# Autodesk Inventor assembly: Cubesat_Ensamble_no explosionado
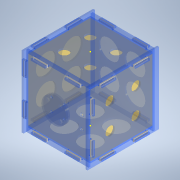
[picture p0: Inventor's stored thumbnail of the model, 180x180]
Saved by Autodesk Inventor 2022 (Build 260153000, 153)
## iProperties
Created: 2022-05
Part Number: Cubesat_Ensamble_no explosionado
Document SubType Name: Assembly
Designer: valen
Author: valen
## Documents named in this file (11)
- C:\Users\valen\Desktop\Estandar CubeSat - Programa AVES-20220531T050024Z-001\Estandar CubeSat - Programa AVES\3D - MODELS\IPT(Autodesk Inventor)\Cubesat_Ensamble_no explosionado.iam
- C:\Users\valen\Desktop\Estandar CubeSat - Programa AVES-20220531T050024Z-001\Estandar CubeSat - Programa AVES\3D - MODELS\IPT(Autodesk Inventor)\Volumen interno .ipt
- C:\Users\valen\Desktop\Estandar CubeSat - Programa AVES-20220531T050024Z-001\Estandar CubeSat - Programa AVES\3D - MODELS\IPT(Autodesk Inventor)\1.Frontal.ipt
- C:\Users\valen\Desktop\Estandar CubeSat - Programa AVES-20220531T050024Z-001\Estandar CubeSat - Programa AVES\3D - MODELS\IPT(Autodesk Inventor)\3.Posterior.ipt
- C:\Users\valen\Desktop\Estandar CubeSat - Programa AVES-20220531T050024Z-001\Estandar CubeSat - Programa AVES\3D - MODELS\IPT(Autodesk Inventor)\2.Lateral derecha .ipt
- C:\Users\valen\Desktop\Estandar CubeSat - Programa AVES-20220531T050024Z-001\Estandar CubeSat - Programa AVES\3D - MODELS\IPT(Autodesk Inventor)\4.Lateral izquierda.ipt
- C:\Users\valen\Desktop\Estandar CubeSat - Programa AVES-20220531T050024Z-001\Estandar CubeSat - Programa AVES\3D - MODELS\IPT(Autodesk Inventor)\6.Inferior.ipt
- C:\Users\valen\Desktop\Estandar CubeSat - Programa AVES-20220531T050024Z-001\Estandar CubeSat - Programa AVES\3D - MODELS\IPT(Autodesk Inventor)\5.Superior.ipt
- C:\Users\valen\Desktop\Estandar CubeSat - Programa AVES-20220531T050024Z-001\Estandar CubeSat - Programa AVES\3D - MODELS\IPT(Autodesk Inventor)\7. Arandela.ipt
- C:\Users\valen\Desktop\Estandar CubeSat - Programa AVES-20220531T050024Z-001\Estandar CubeSat - Programa AVES\3D - MODELS\IPT(Autodesk Inventor)\8. Soporte tuercas.ipt
- C:\Users\valen\Desktop\Estandar CubeSat - Programa AVES-20220531T050024Z-001\Estandar CubeSat - Programa AVES\3D - MODELS\IPT(Autodesk Inventor)\Oring.ipt
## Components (29 placed, 10 different names)
1. Volumen interno :1 — Flush:1, Mate:1, Flush:2, Flush:3, Flush:4, Mate:2, Flush:5, Mate:3, Mate:4, Mate:5, Mate:6, Mate:7, Flush:7, Flush:8, Mate:8, Flush:9
2. 1.Frontal:1 — Flush:1, Mate:1, Flush:3, Flush:10, Mate:16, Mate:18, Mate:20, Mate:22, Mate:24
3. 2.Lateral derecha :1 — Mate:3, Mate:4, Mate:5, Flush:6, Mate:23, Flush:14, Mate:25, Flush:15, Mate:27, Flush:16, Mate:29, Flush:17, Mate:39, Flush:22, Mate:41, Flush:23, Mate:47, Flush:26, Mate:49, Flush:27
4. 3.Posterior:1 — Flush:4, Mate:2, Flush:5, Mate:26, Mate:28, Mate:30, Mate:32, Mate:34, Mate:36
5. 4.Lateral izquierda:1 — Mate:6, Mate:7, Flush:6, Mate:17, Flush:11, Mate:35, Flush:20, Mate:37, Flush:21, Mate:43, Flush:24, Mate:45, Flush:25, Mate:51, Flush:28, Mate:53, Flush:29
6. 5.Superior:1 — Flush:9, Mate:38, Mate:40, Mate:42, Mate:44
7. 6.Inferior:1 — Flush:7, Flush:8, Mate:8, Mate:11, Mate:12, Mate:13, Mate:19, Flush:12, Mate:21, Flush:13, Mate:31, Flush:18, Mate:33, Flush:19, Mate:46, Mate:48, Mate:50, Mate:52
8. 7. Arandela:1 — Mate:11, Mate:12, Mate:13, Mate:14, Mate:15
9. 8. Soporte tuercas:1 — Mate:14, Mate:15
10. Oring:1 — Flush:10
11. Oring:2 — Mate:16, Mate:17, Flush:11
12. Oring:3 — Mate:18, Mate:19, Flush:12
13. Oring:4 — Mate:20, Mate:21, Flush:13
14. Oring:5 — Mate:22, Mate:23, Flush:14
15. Oring:6 — Mate:24, Mate:25, Flush:15
16. Oring:7 — Mate:26, Mate:27, Flush:16
17. Oring:8 — Mate:36, Mate:37, Flush:21
18. Oring:9 — Mate:32, Mate:33, Flush:19
19. Oring:10 — Mate:34, Mate:35, Flush:20
20. Oring:11 — Mate:30, Mate:31, Flush:18
21. Oring:12 — Mate:28, Mate:29, Flush:17
22. Oring:13 — Mate:40, Mate:41, Flush:23
23. Oring:14 — Mate:42, Mate:43, Flush:24
24. Oring:15 — Mate:38, Mate:39, Flush:22
25. Oring:16 — Mate:44, Mate:45, Flush:25
26. Oring:17 — Mate:48, Mate:49, Flush:27
27. Oring:18 — Mate:46, Mate:47, Flush:26
28. Oring:19 — Mate:52, Mate:53, Flush:29
29. Oring:20 — Mate:50, Mate:51, Flush:28
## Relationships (80: Mate 51, Flush 29)
- Flush:1: Volumen interno :1 ↔ 1.Frontal:1
- Mate:1: Volumen interno :1 ↔ 1.Frontal:1
- Flush:2: Volumen interno :1
- Flush:3: Volumen interno :1 ↔ 1.Frontal:1
- Flush:4: Volumen interno :1 ↔ 3.Posterior:1
- Mate:2: Volumen interno :1 ↔ 3.Posterior:1
- Flush:5: Volumen interno :1 ↔ 3.Posterior:1
- Mate:3: Volumen interno :1 ↔ 2.Lateral derecha :1
- Mate:4: Volumen interno :1 ↔ 2.Lateral derecha :1
- Mate:5: Volumen interno :1 ↔ 2.Lateral derecha :1
- Mate:6: Volumen interno :1 ↔ 4.Lateral izquierda:1
- Mate:7: Volumen interno :1 ↔ 4.Lateral izquierda:1
- Flush:6: 2.Lateral derecha :1 ↔ 4.Lateral izquierda:1
- Flush:7: Volumen interno :1 ↔ 6.Inferior:1
- Flush:8: Volumen interno :1 ↔ 6.Inferior:1
- Mate:8: Volumen interno :1 ↔ 6.Inferior:1
- Flush:9: Volumen interno :1 ↔ 5.Superior:1
- Mate:11: 6.Inferior:1 ↔ 7. Arandela:1
- Mate:12: 6.Inferior:1 ↔ 7. Arandela:1
- Mate:13: 6.Inferior:1 ↔ 7. Arandela:1
- Mate:14: 7. Arandela:1 ↔ 8. Soporte tuercas:1
- Mate:15: 7. Arandela:1 ↔ 8. Soporte tuercas:1
- Flush:10: 1.Frontal:1 ↔ Oring:1
- Mate:16: 1.Frontal:1 ↔ Oring:2
- Mate:17: 4.Lateral izquierda:1 ↔ Oring:2
- Flush:11: 4.Lateral izquierda:1 ↔ Oring:2
- Mate:18: 1.Frontal:1 ↔ Oring:3
- Mate:19: 6.Inferior:1 ↔ Oring:3
- Flush:12: 6.Inferior:1 ↔ Oring:3
- Mate:20: 1.Frontal:1 ↔ Oring:4
- Mate:21: 6.Inferior:1 ↔ Oring:4
- Flush:13: 6.Inferior:1 ↔ Oring:4
- Mate:22: 1.Frontal:1 ↔ Oring:5
- Mate:23: 2.Lateral derecha :1 ↔ Oring:5
- Flush:14: 2.Lateral derecha :1 ↔ Oring:5
- Mate:24: 1.Frontal:1 ↔ Oring:6
- Mate:25: 2.Lateral derecha :1 ↔ Oring:6
- Flush:15: 2.Lateral derecha :1 ↔ Oring:6
- Mate:26: 3.Posterior:1 ↔ Oring:7
- Mate:27: 2.Lateral derecha :1 ↔ Oring:7
- Flush:16: 2.Lateral derecha :1 ↔ Oring:7
- Mate:28: 3.Posterior:1 ↔ Oring:12
- Mate:29: 2.Lateral derecha :1 ↔ Oring:12
- Flush:17: 2.Lateral derecha :1 ↔ Oring:12
- Mate:30: 3.Posterior:1 ↔ Oring:11
- Mate:31: 6.Inferior:1 ↔ Oring:11
- Flush:18: 6.Inferior:1 ↔ Oring:11
- Mate:32: 3.Posterior:1 ↔ Oring:9
- Mate:33: 6.Inferior:1 ↔ Oring:9
- Flush:19: 6.Inferior:1 ↔ Oring:9
- Mate:34: 3.Posterior:1 ↔ Oring:10
- Mate:35: 4.Lateral izquierda:1 ↔ Oring:10
- Flush:20: 4.Lateral izquierda:1 ↔ Oring:10
- Mate:36: 3.Posterior:1 ↔ Oring:8
- Mate:37: 4.Lateral izquierda:1 ↔ Oring:8
- Flush:21: 4.Lateral izquierda:1 ↔ Oring:8
- Mate:38: 5.Superior:1 ↔ Oring:15
- Mate:39: 2.Lateral derecha :1 ↔ Oring:15
- Flush:22: 2.Lateral derecha :1 ↔ Oring:15
- Mate:40: 5.Superior:1 ↔ Oring:13
- Mate:41: 2.Lateral derecha :1 ↔ Oring:13
- Flush:23: 2.Lateral derecha :1 ↔ Oring:13
- Mate:42: 5.Superior:1 ↔ Oring:14
- Mate:43: 4.Lateral izquierda:1 ↔ Oring:14
- Flush:24: 4.Lateral izquierda:1 ↔ Oring:14
- Mate:44: 5.Superior:1 ↔ Oring:16
- Mate:45: 4.Lateral izquierda:1 ↔ Oring:16
- Flush:25: 4.Lateral izquierda:1 ↔ Oring:16
- Mate:46: 6.Inferior:1 ↔ Oring:18
- Mate:47: 2.Lateral derecha :1 ↔ Oring:18
- Flush:26: 2.Lateral derecha :1 ↔ Oring:18
- Mate:48: 6.Inferior:1 ↔ Oring:17
- Mate:49: 2.Lateral derecha :1 ↔ Oring:17
- Flush:27: 2.Lateral derecha :1 ↔ Oring:17
- Mate:50: 6.Inferior:1 ↔ Oring:20
- Mate:51: 4.Lateral izquierda:1 ↔ Oring:20
- Flush:28: 4.Lateral izquierda:1 ↔ Oring:20
- Mate:52: 6.Inferior:1 ↔ Oring:19
- Mate:53: 4.Lateral izquierda:1 ↔ Oring:19
- Flush:29: 4.Lateral izquierda:1 ↔ Oring:19
